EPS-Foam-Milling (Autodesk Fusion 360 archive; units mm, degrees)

design "Foam Storage Pieces" references "autodesk generic router xyz"
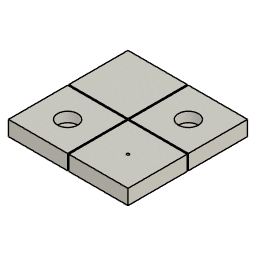
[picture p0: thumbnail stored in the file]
sketch "Sketch1" plane through (0, 0, 0) normal (0, 0, 1) x axis (1, 0, 0)
  line L1 (304.8, 0) -> (0, 0)
  line L2 (304.8, 304.8) -> (304.8, 0)
  line L3 (0, 304.8) -> (304.8, 304.8)
  line L4 (0, 0) -> (0, 304.8)
  point P1 (0, 0)
  point P2 (0, 0)
  point P3 (304.8, 0)
  point P5 (0, 304.8)
  horizontal L1
  vertical L2
  horizontal L3
  vertical L4
  coincident P1 P2
  dimension "d1" distance P2 P3 = 304.8
  dimension "d2" distance P2 P5 = 304.8
extrude "Extrude1" new body sketch "Sketch1" along normal blind 38.1
sketch "Sketch2" plane through (0, 0, 38.1) normal (0, 0, 1) x axis (-1, 0, 0)
  line L1 (0, 0) -> (0, -304.8)
  line L2 (-304.8, 0) -> (0, 0)
  line L3 (-304.8, -304.8) -> (-304.8, 0)
  line L4 (0, -304.8) -> (-304.8, -304.8)
  line L5 (-152.4, -304.8) -> (0, -304.8)
  line L6 (-152.4, 0) -> (-152.4, -304.8)
  line L7 (0, -152.4) -> (0, -304.8)
  line L8 (-304.8, -152.4) -> (0, -152.4)
  line L9 (-153.9875, -304.8) -> (-152.4, -304.8)
  line L10 (-150.8125, -304.8) -> (-152.4, -304.8)
  line L11 (-153.9875, 0) -> (-153.9875, -304.8)
  line L12 (-150.8125, 0) -> (-150.8125, -304.8)
  line L13 (0, -153.9875) -> (0, -152.4)
  line L14 (0, -150.8125) -> (0, -152.4)
  line L15 (-304.8, -153.9875) -> (0, -153.9875)
  line L16 (-304.8, -150.8125) -> (0, -150.8125)
  point P2 (0, -304.8)
  point P6 (0, -304.8)
  point P8 (-152.4, 0)
  point P10 (-304.8, -152.4)
  point P7 (-152.4, -304.8)
  point P9 (0, -152.4)
  point P11 (-153.9875, -304.8)
  point P12 (-150.8125, -304.8)
  point P13 (-153.9875, 0)
  point P14 (-150.8125, 0)
  point P15 (0, -153.9875)
  point P16 (0, -150.8125)
  point P17 (-304.8, -153.9875)
  point P18 (-304.8, -150.8125)
  coincident P2 P6
  perpendicular L1 L5
  midpoint L2 P8
  perpendicular L5 L7
  midpoint L3 P10
  horizontal L9
  horizontal L10
  perpendicular L9 L11
  perpendicular L10 L12
  vertical L13
  vertical L14
  perpendicular L13 L15
  perpendicular L7 L16
  dimension "d5" distance P6 P7 = 152.4
  dimension "d6" distance P6 P9 = 152.4
  dimension "d7" distance P7 P11 = 1.5875
  dimension "d8" distance P7 P12 = 1.5875
  dimension "d9" distance P11 P13 = 304.8
  dimension "d10" distance P12 P14 = 304.8
  dimension "d11" distance P9 P15 = 1.5875
  dimension "d12" distance P9 P16 = 1.5875
  dimension "d13" distance P15 P17 = 304.8
  dimension "d14" distance P16 P18 = 304.8
extrude "Extrude2" cut sketch "Sketch2" against normal blind 38.1
sketch "Sketch5" plane through (0, 0, 38.1) normal (0, 0, 1) x axis (-1, 0, 0)
  line L1 (-304.8, -153.9875) -> (-153.9875, -153.9875)
  line L2 (-304.8, -304.8) -> (-304.8, -153.9875)
  line L3 (-153.9875, -304.8) -> (-304.8, -304.8)
  line L4 (-153.9875, -153.9875) -> (-153.9875, -304.8)
  line L5 (-304.8, -229.3938) -> (-304.8, -304.8)
  line L6 (-229.3938, -229.3938) -> (-304.8, -229.3938)
  circle C1 centre (-229.3938, -229.3938) radius 25.5
  point P4 (-304.8, -304.8)
  point P6 (-304.8, -304.8)
  point P7 (-304.8, -229.3938)
  point P8 (-229.3938, -229.3938)
  point P9 (-229.3938, -229.3938)
  coincident P4 P6
  midpoint L2 P7
  perpendicular L5 L6
  coincident P8 P9
  dimension "d23" diameter C1 = 51
extrude "Extrude5" cut sketch "Sketch5" profile of C1 against normal blind 25.4
sketch "Sketch11" plane through (0, 0, 12.7) normal (0, 0, 1) x axis (-1, 0, 0)
  circle C1 centre (-229.3938, -229.3938) radius 25.5
  circle C2 centre (-229.3938, -229.3938) radius 8.75
  concentric C1 C2
  dimension "d41" diameter C2 = 17.5
extrude "Extrude11" cut sketch "Sketch11" profile of C2 against normal blind 1.15
sketch "Sketch12" plane through (0, 0, 11.55) normal (0, 0, 1) x axis (-1, 0, 0)
  circle C1 centre (-229.3938, -229.3938) radius 8.75
  circle C2 centre (-229.3938, -229.3938) radius 6.425
  concentric C1 C2
  dimension "d44" diameter C2 = 12.85
extrude "Extrude12" cut sketch "Sketch12" profile of C2 against normal blind 4.775
sketch "Sketch6" plane through (0, 0, 38.1) normal (0, 0, 1) x axis (-1, 0, 0)
  line L1 (-150.8125, -150.8125) -> (-150.8125, 0)
  line L2 (0, -150.8125) -> (-150.8125, -150.8125)
  line L3 (0, 0) -> (0, -150.8125)
  line L4 (-150.8125, 0) -> (0, 0)
  line L5 (0, -75.4063) -> (0, 0)
  line L6 (-75.4063, -75.4063) -> (0, -75.4063)
  circle C1 centre (-75.4063, -75.4063) radius 25.5
  point P5 (0, 0)
  point P6 (0, 0)
  point P7 (0, -75.4063)
  point P8 (-75.4063, -75.4063)
  point P9 (-75.4063, -75.4063)
  coincident P5 P6
  midpoint L3 P7
  perpendicular L5 L6
  coincident P8 P9
  dimension "d26" diameter C1 = 51
extrude "Extrude6" cut sketch "Sketch6" profile of C1 against normal blind 25.4
sketch "Sketch7" plane through (0, 0, 12.7) normal (0, 0, 1) x axis (-1, 0, 0)
  circle C1 centre (-75.4063, -75.4063) radius 25.5
  circle C2 centre (-75.4063, -75.4063) radius 8.75
  concentric C1 C2
  dimension "d29" diameter C2 = 17.5
extrude "Extrude7" cut sketch "Sketch7" profile of C2 against normal blind 1.15
sketch "Sketch8" plane through (0, 0, 11.55) normal (0, 0, 1) x axis (-1, 0, 0)
  circle C1 centre (-75.4063, -75.4063) radius 8.75
  circle C2 centre (-75.4063, -75.4063) radius 6.425
  concentric C1 C2
  dimension "d32" diameter C2 = 12.85
extrude "Extrude8" cut sketch "Sketch8" profile of C2 against normal blind 4.775
sketch "Sketch9" plane through (0, 0, 6.775) normal (0, 0, 1) x axis (-1, 0, 0)
  circle C1 centre (-75.4063, -75.4063) radius 6.425
  circle C2 centre (-75.4063, -75.4063) radius 3.25
  concentric C1 C2
  dimension "d35" diameter C2 = 6.5
extrude "Extrude9" cut sketch "Sketch9" profile of C2 against normal blind 38.1
sketch "Sketch10" plane through (0, 0, 38.1) normal (0, 0, 1) x axis (-1, 0, 0)
  line L1 (-153.9875, -150.8125) -> (-304.8, -150.8125)
  line L2 (-153.9875, 0) -> (-153.9875, -150.8125)
  line L3 (-304.8, 0) -> (-153.9875, 0)
  line L4 (-304.8, -150.8125) -> (-304.8, 0)
  line L5 (-304.8, -75.4063) -> (-304.8, 0)
  line L6 (-229.3938, -75.4063) -> (-304.8, -75.4063)
  circle C1 centre (-229.3938, -75.4063) radius 3.25
  point P5 (-304.8, 0)
  point P6 (-304.8, 0)
  point P7 (-304.8, -75.4063)
  point P8 (-229.3938, -75.4063)
  point P9 (-229.3938, -75.4063)
  coincident P5 P6
  midpoint L4 P7
  perpendicular L4 L6
  coincident P8 P9
  dimension "d38" diameter C1 = 6.5
extrude "Extrude10" cut sketch "Sketch10" profile of C1 against normal blind 38.1

design "autodesk generic router xyz"
named bodies: "static", "x_axis_head", "y_axis_head", "z_axis_head"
